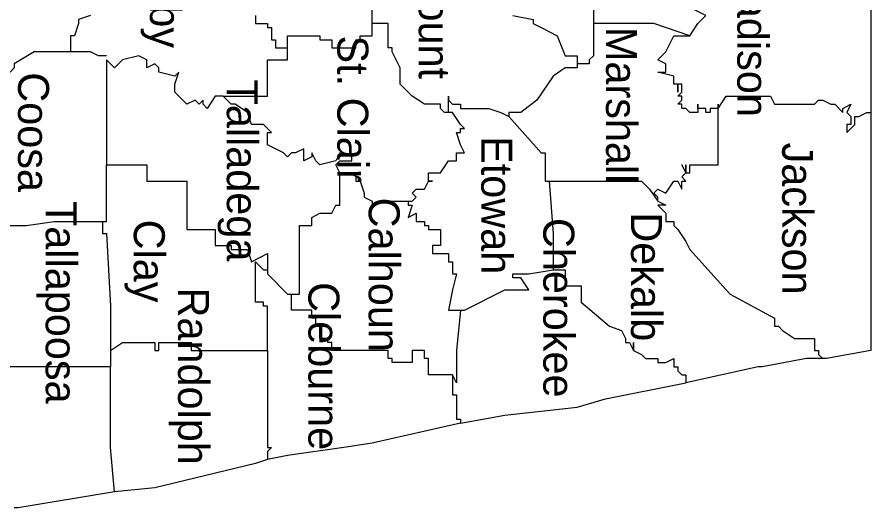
# Model space of a CAD drawing. Extents: x 0 to 0.917, y 0 to 0.708.
# Drawn here: x 0.4862 to 0.6298, y 0.4444 to 0.5269 of the extents above; entities that cross this region are included whole.
import ezdxf

# ---------------------------------------------------------------- set-up
doc = ezdxf.new("R2010")
doc.units = 0
doc.layers.add('ANNO-SHT', color=7, linetype='Continuous')
doc.layers.add('ANNO-TXT', color=7, linetype='Continuous')

msp = doc.modelspace()

# ---------------------------------------------------------------- linework, layer by layer
at = {"layer": 'ANNO-SHT'}
for points in [[(0.62981, 0.5618), (0.62981, 0.55161), (0.62981, 0.54347), (0.62981, 0.54143), (0.62981, 0.53736), (0.62981, 0.52718), (0.62981, 0.51089), (0.62981, 0.5075), (0.62981, 0.49732), (0.62981, 0.48781), (0.62981, 0.47763), (0.62981, 0.47085), (0.62981, 0.47085), (0.62236, 0.46949), (0.62169, 0.46949), (0.61898, 0.46949), (0.61154, 0.46813), (0.61086, 0.46813), (0.59868, 0.46542), (0.59868, 0.46542)], [(0.58312, 0.55637), (0.58312, 0.55501), (0.58312, 0.54958), (0.58312, 0.54415), (0.58312, 0.54347), (0.58312, 0.52718), (0.58312, 0.52582)], [(0.59936, 0.52379), (0.60071, 0.52582), (0.60206, 0.52718), (0.59936, 0.52854), (0.60003, 0.53057), (0.60206, 0.53261), (0.60206, 0.53397), (0.59936, 0.53533), (0.59936, 0.53736), (0.59936, 0.53804), (0.60003, 0.54143), (0.60206, 0.54415), (0.60409, 0.5489), (0.60545, 0.54958), (0.6068, 0.55161), (0.60612, 0.55229), (0.60748, 0.55501), (0.60815, 0.55637)], [(0.55876, 0.51089), (0.55808, 0.51089), (0.55808, 0.51089), (0.55808, 0.51089), (0.5574, 0.51157), (0.5574, 0.51225), (0.55605, 0.51225), (0.55537, 0.51225), (0.55537, 0.51225), (0.55537, 0.51225), (0.5547, 0.51225), (0.55267, 0.51361), (0.55064, 0.51564), (0.55064, 0.51768), (0.55064, 0.51836), (0.54928, 0.52107), (0.54928, 0.52175), (0.54861, 0.52175), (0.54861, 0.52175), (0.54861, 0.52582), (0.5459, 0.52582), (0.5459, 0.52854)], [(0.49853, 0.52718), (0.4965, 0.5265), (0.4965, 0.5265), (0.4965, 0.52582), (0.49583, 0.52379), (0.49515, 0.52379), (0.49515, 0.52311), (0.49515, 0.52175), (0.49515, 0.52175), (0.49515, 0.52107)], [(0.49853, 0.52718), (0.4965, 0.5265), (0.4965, 0.5265), (0.4965, 0.52582), (0.49583, 0.52379), (0.49515, 0.52379), (0.49515, 0.52311), (0.49515, 0.52175), (0.49515, 0.52175), (0.49515, 0.52107)], [(0.52628, 0.52718), (0.52628, 0.5265), (0.52628, 0.5265), (0.52628, 0.52582), (0.52763, 0.52582), (0.52763, 0.52582), (0.52831, 0.52582), (0.52831, 0.52582), (0.52831, 0.52582), (0.52831, 0.52514), (0.52898, 0.52514), (0.52898, 0.52379), (0.52898, 0.52379), (0.52898, 0.52379), (0.52898, 0.52311), (0.52966, 0.52311), (0.52966, 0.52175), (0.53169, 0.52175)], [(0.56958, 0.52718), (0.57297, 0.5265), (0.57297, 0.52582), (0.57432, 0.52514), (0.57703, 0.52379), (0.57838, 0.52039), (0.58041, 0.52039), (0.58041, 0.51904), (0.58041, 0.51836), (0.57838, 0.51836), (0.57635, 0.517), (0.57364, 0.51293), (0.57094, 0.51089), (0.56958, 0.51089), (0.56958, 0.51089), (0.56891, 0.51089), (0.56891, 0.51021)], [(0.52086, 0.51361), (0.52492, 0.51361), (0.52831, 0.51361), (0.52831, 0.51971), (0.53169, 0.51971), (0.53169, 0.52175), (0.53169, 0.52175), (0.53169, 0.52175), (0.53169, 0.52311), (0.53169, 0.52379), (0.53237, 0.52379), (0.53237, 0.52379), (0.53575, 0.52379), (0.53643, 0.52379), (0.5371, 0.52379), (0.5371, 0.52311), (0.53913, 0.52311), (0.53913, 0.52175), (0.54116, 0.52175), (0.54116, 0.52175), (0.54319, 0.52175), (0.54319, 0.52311), (0.54387, 0.52311), (0.54387, 0.52379), (0.5459, 0.52379), (0.5459, 0.52582)], [(0.59936, 0.52379), (0.59327, 0.52582), (0.58785, 0.52582), (0.58312, 0.52582), (0.58312, 0.52379), (0.58312, 0.52107), (0.58312, 0.52039), (0.58244, 0.51971), (0.58244, 0.51904), (0.58109, 0.51904), (0.58109, 0.51904), (0.58041, 0.51904), (0.58041, 0.51904), (0.58041, 0.51904)], [(0.57567, 0.49935), (0.58041, 0.49935), (0.58176, 0.49935), (0.58312, 0.49935), (0.58988, 0.49935), (0.58988, 0.49935), (0.58988, 0.49935), (0.58988, 0.49935), (0.59124, 0.49935), (0.59259, 0.498), (0.59394, 0.49596), (0.59394, 0.49664), (0.59327, 0.49732), (0.59394, 0.498), (0.5953, 0.49732), (0.59665, 0.49935), (0.59733, 0.49935), (0.59733, 0.49935), (0.598, 0.498), (0.598, 0.49935), (0.59868, 0.49935), (0.598, 0.50003), (0.59868, 0.50071), (0.598, 0.50207), (0.59868, 0.50071), (0.59868, 0.50207), (0.59868, 0.50207), (0.59868, 0.50207), (0.59868, 0.50207), (0.59868, 0.50207), (0.59868, 0.50207), (0.59868, 0.50071), (0.59936, 0.50071), (0.59936, 0.50207), (0.60003, 0.50207), (0.60003, 0.50207), (0.60409, 0.50207), (0.60409, 0.51157), (0.60274, 0.51157), (0.60274, 0.51089), (0.60274, 0.51089), (0.60274, 0.51089), (0.60206, 0.51089), (0.60206, 0.51089), (0.60206, 0.51157), (0.60071, 0.51157), (0.60071, 0.51225), (0.60071, 0.51225), (0.60071, 0.51089), (0.59936, 0.51089), (0.59936, 0.51089), (0.59868, 0.51157), (0.598, 0.51157), (0.598, 0.51225), (0.59733, 0.51225), (0.59733, 0.51225), (0.59733, 0.51225), (0.598, 0.51293), (0.598, 0.51361), (0.59733, 0.51361), (0.598, 0.51428), (0.598, 0.51564), (0.598, 0.51564), (0.59733, 0.51564), (0.59733, 0.51564), (0.59733, 0.51428), (0.59733, 0.51564), (0.59665, 0.51564), (0.59665, 0.51564), (0.59665, 0.51564), (0.59665, 0.51564), (0.59665, 0.517), (0.59394, 0.51768), (0.5953, 0.51768), (0.5953, 0.51904), (0.59394, 0.51971), (0.59394, 0.51971), (0.5953, 0.52107), (0.59665, 0.52379), (0.59733, 0.52379), (0.59868, 0.52379), (0.59936, 0.52379)], [(0.49515, 0.52107), (0.49312, 0.52107), (0.49244, 0.52107), (0.49109, 0.52107), (0.48974, 0.52107), (0.48906, 0.52107), (0.48568, 0.51904), (0.48568, 0.51836), (0.485, 0.51768), (0.48432, 0.51768), (0.48432, 0.51768), (0.48162, 0.51768), (0.47959, 0.517), (0.47959, 0.51564), (0.47891, 0.51564), (0.47756, 0.51293)], [(0.49515, 0.52107), (0.49312, 0.52107), (0.49244, 0.52107), (0.49109, 0.52107), (0.48974, 0.52107), (0.48906, 0.52107), (0.48568, 0.51904), (0.48568, 0.51836), (0.485, 0.51768), (0.48432, 0.51768), (0.48432, 0.51768), (0.48162, 0.51768), (0.47959, 0.517), (0.47959, 0.51564), (0.47891, 0.51564), (0.47756, 0.51293)], [(0.50124, 0.52039), (0.50056, 0.52039), (0.49989, 0.52039), (0.49853, 0.52107), (0.4965, 0.52107), (0.49515, 0.52107)], [(0.50124, 0.52039), (0.50056, 0.52039), (0.49989, 0.52039), (0.49853, 0.52107), (0.4965, 0.52107), (0.49515, 0.52107)], [(0.54049, 0.50071), (0.54049, 0.50071), (0.53981, 0.50207), (0.54049, 0.50275), (0.54252, 0.50275), (0.54252, 0.50343), (0.54049, 0.5041), (0.53981, 0.50275), (0.5371, 0.50207), (0.53643, 0.50275), (0.53575, 0.5041), (0.53575, 0.50343), (0.5344, 0.50275), (0.5344, 0.50275), (0.5344, 0.50275), (0.5344, 0.50478), (0.53304, 0.5041), (0.53237, 0.5041), (0.53169, 0.50343), (0.53101, 0.5041), (0.52966, 0.50478), (0.52831, 0.50546), (0.52831, 0.5075), (0.52898, 0.5075), (0.52763, 0.50886), (0.5256, 0.50886), (0.52492, 0.51089), (0.52289, 0.51225), (0.52222, 0.51225), (0.52086, 0.51361), (0.51951, 0.51361), (0.51816, 0.51157), (0.51748, 0.51225), (0.51748, 0.51293), (0.5168, 0.51225), (0.51613, 0.51293), (0.51477, 0.51225), (0.51477, 0.51225), (0.51274, 0.51428), (0.51274, 0.51564), (0.51342, 0.51768), (0.51274, 0.517), (0.51004, 0.51768), (0.51004, 0.51836), (0.50936, 0.51904), (0.50801, 0.51836), (0.50801, 0.51904), (0.50801, 0.51971), (0.50665, 0.52039), (0.50665, 0.52039), (0.50395, 0.51971), (0.50327, 0.51904), (0.50259, 0.51836), (0.50192, 0.51904), (0.50124, 0.51971)], [(0.54049, 0.50071), (0.54049, 0.50071), (0.53981, 0.50207), (0.54049, 0.50275), (0.54252, 0.50275), (0.54252, 0.50343), (0.54049, 0.5041), (0.53981, 0.50275), (0.5371, 0.50207), (0.53643, 0.50275), (0.53575, 0.5041), (0.53575, 0.50343), (0.5344, 0.50275), (0.5344, 0.50275), (0.5344, 0.50275), (0.5344, 0.50478), (0.53304, 0.5041), (0.53237, 0.5041), (0.53169, 0.50343), (0.53101, 0.5041), (0.52966, 0.50478), (0.52831, 0.50546), (0.52831, 0.5075), (0.52898, 0.5075), (0.52763, 0.50886), (0.5256, 0.50886), (0.52492, 0.51089), (0.52289, 0.51225), (0.52222, 0.51225), (0.52086, 0.51361), (0.51951, 0.51361), (0.51816, 0.51157), (0.51748, 0.51225), (0.51748, 0.51293), (0.5168, 0.51225), (0.51613, 0.51293), (0.51477, 0.51225), (0.51477, 0.51225), (0.51274, 0.51428), (0.51274, 0.51564), (0.51342, 0.51768), (0.51274, 0.517), (0.51004, 0.51768), (0.51004, 0.51836), (0.50936, 0.51904), (0.50801, 0.51836), (0.50801, 0.51904), (0.50801, 0.51971), (0.50665, 0.52039), (0.50665, 0.52039), (0.50395, 0.51971), (0.50327, 0.51904), (0.50259, 0.51836), (0.50192, 0.51904), (0.50124, 0.51971)], [(0.50124, 0.51971), (0.50124, 0.50546), (0.50124, 0.50478), (0.50124, 0.50207)], [(0.55199, 0.49596), (0.55199, 0.49596), (0.55199, 0.49596), (0.55199, 0.49596), (0.55267, 0.49596), (0.55267, 0.49596), (0.55334, 0.49664), (0.55267, 0.49732), (0.55267, 0.49732), (0.55267, 0.49732), (0.55334, 0.498), (0.5547, 0.498), (0.55537, 0.49935), (0.55605, 0.49935), (0.55537, 0.49935), (0.55537, 0.50003), (0.55537, 0.50071), (0.55605, 0.50071), (0.5574, 0.50071), (0.55876, 0.50275), (0.55943, 0.50275), (0.56011, 0.50275), (0.56011, 0.5041), (0.56079, 0.5041), (0.56146, 0.5041), (0.56079, 0.50546), (0.56079, 0.50546), (0.56011, 0.5075), (0.56079, 0.5075), (0.56079, 0.50818), (0.56146, 0.50818), (0.56079, 0.50886), (0.56079, 0.50886), (0.55943, 0.51089), (0.55876, 0.51089), (0.55876, 0.51361), (0.55876, 0.51361), (0.55876, 0.51293), (0.55943, 0.51225), (0.55943, 0.51225), (0.55943, 0.51225), (0.55943, 0.51225), (0.56011, 0.51225), (0.56011, 0.51225), (0.56011, 0.51225), (0.56079, 0.51225), (0.56079, 0.51157), (0.56079, 0.51157), (0.56146, 0.51157), (0.56417, 0.51157), (0.56552, 0.51157), (0.56755, 0.51089), (0.56755, 0.51089), (0.56891, 0.51021)], [(0.60409, 0.51157), (0.60409, 0.51225), (0.60409, 0.51157), (0.60545, 0.51361), (0.60883, 0.51361), (0.61289, 0.51361), (0.61357, 0.51225), (0.61424, 0.51225), (0.61492, 0.51225), (0.6156, 0.51225), (0.6156, 0.51225), (0.61695, 0.51225), (0.61695, 0.51225), (0.61763, 0.51225), (0.6183, 0.51225), (0.61898, 0.51225), (0.61898, 0.51225), (0.62033, 0.51225), (0.62101, 0.51293), (0.62169, 0.51293), (0.62169, 0.51293), (0.62304, 0.51225), (0.62304, 0.51225), (0.62372, 0.51225), (0.62507, 0.51089), (0.62507, 0.51157), (0.62642, 0.51225), (0.62575, 0.51089), (0.62642, 0.51021), (0.62642, 0.51021), (0.62642, 0.50886), (0.62575, 0.50886), (0.62575, 0.50886), (0.62575, 0.50886), (0.62575, 0.50818), (0.62575, 0.5075), (0.62642, 0.50818), (0.6271, 0.50886), (0.6271, 0.51021), (0.62778, 0.51021), (0.62913, 0.51089), (0.62981, 0.51089)], [(0.56891, 0.51021), (0.57432, 0.5041), (0.575, 0.5041), (0.575, 0.50343), (0.575, 0.50275), (0.575, 0.50275), (0.575, 0.50207), (0.575, 0.50071), (0.575, 0.49935), (0.57567, 0.49935), (0.57635, 0.49053), (0.57635, 0.48917), (0.57635, 0.48781), (0.57635, 0.48442), (0.57838, 0.48442), (0.57838, 0.48306), (0.57838, 0.48306), (0.57838, 0.48171), (0.57838, 0.48171), (0.58109, 0.48171), (0.58109, 0.47899), (0.58582, 0.47492), (0.58785, 0.47424), (0.58853, 0.47288), (0.58853, 0.47288), (0.58853, 0.4722), (0.58853, 0.4722), (0.58921, 0.4722), (0.58988, 0.47085), (0.58988, 0.4722), (0.58988, 0.47085), (0.58988, 0.47085), (0.59124, 0.47017), (0.59124, 0.47017), (0.59191, 0.46949), (0.59191, 0.46949), (0.59191, 0.46949), (0.59394, 0.46949), (0.59394, 0.46949), (0.59394, 0.46949), (0.59394, 0.46881), (0.5953, 0.46881), (0.59665, 0.46949), (0.59665, 0.46813), (0.59733, 0.46813), (0.59733, 0.46745), (0.598, 0.46677), (0.598, 0.46677), (0.59868, 0.46677), (0.59868, 0.46677), (0.59868, 0.46542)], [(0.56891, 0.51021), (0.57432, 0.5041), (0.575, 0.5041), (0.575, 0.50343), (0.575, 0.50275), (0.575, 0.50275), (0.575, 0.50207), (0.575, 0.50071), (0.575, 0.49935), (0.57567, 0.49935), (0.57635, 0.49053), (0.57635, 0.48917), (0.57635, 0.48781), (0.57635, 0.48442), (0.57838, 0.48442), (0.57838, 0.48306), (0.57838, 0.48306), (0.57838, 0.48171), (0.57838, 0.48171), (0.58109, 0.48171), (0.58109, 0.47899), (0.58582, 0.47492), (0.58785, 0.47424), (0.58853, 0.47288), (0.58853, 0.47288), (0.58853, 0.4722), (0.58853, 0.4722), (0.58921, 0.4722), (0.58988, 0.47085), (0.58988, 0.4722), (0.58988, 0.47085), (0.58988, 0.47085), (0.59124, 0.47017), (0.59124, 0.47017), (0.59191, 0.46949), (0.59191, 0.46949), (0.59191, 0.46949), (0.59394, 0.46949), (0.59394, 0.46949), (0.59394, 0.46949), (0.59394, 0.46881), (0.5953, 0.46881), (0.59665, 0.46949), (0.59665, 0.46813), (0.59733, 0.46813), (0.59733, 0.46745), (0.598, 0.46677), (0.598, 0.46677), (0.59868, 0.46677), (0.59868, 0.46677), (0.59868, 0.46542)], [(0.47756, 0.49189), (0.48162, 0.49189), (0.48297, 0.49257), (0.48297, 0.49189), (0.48297, 0.49189), (0.48297, 0.49257), (0.48297, 0.49257), (0.48297, 0.49189), (0.48703, 0.49189), (0.48771, 0.49189), (0.49244, 0.49257), (0.50056, 0.49257), (0.50124, 0.49257), (0.50124, 0.49257), (0.50124, 0.50207)], [(0.50124, 0.50207), (0.50665, 0.50207), (0.50801, 0.50207), (0.50801, 0.49935), (0.51477, 0.49935), (0.51477, 0.49257), (0.51477, 0.49189), (0.51477, 0.49121), (0.51951, 0.49121), (0.51951, 0.48849), (0.52222, 0.48849), (0.52222, 0.48781), (0.52492, 0.48781), (0.5256, 0.48578), (0.52831, 0.48714), (0.52831, 0.48374), (0.53169, 0.48035), (0.53237, 0.48035), (0.53372, 0.48035), (0.53372, 0.48374), (0.53372, 0.4851), (0.53372, 0.49189), (0.53575, 0.49189), (0.53575, 0.49324), (0.53575, 0.49324), (0.53575, 0.49324), (0.5371, 0.49392), (0.53846, 0.49392), (0.53846, 0.49392), (0.53913, 0.49392), (0.53913, 0.49392), (0.53981, 0.49528), (0.54049, 0.49528), (0.54049, 0.49664), (0.54049, 0.50071)], [(0.54049, 0.50071), (0.54252, 0.50071), (0.54319, 0.50003), (0.54319, 0.49935), (0.54387, 0.49935), (0.54455, 0.49732), (0.54455, 0.49664), (0.5459, 0.49596), (0.5459, 0.49528), (0.54793, 0.49596), (0.54793, 0.49596), (0.54861, 0.49596), (0.54928, 0.49596), (0.55064, 0.49596), (0.55131, 0.49596), (0.55199, 0.49596)], [(0.55199, 0.49596), (0.55199, 0.49596), (0.55199, 0.49528), (0.55267, 0.49528), (0.55199, 0.49324), (0.55334, 0.49392), (0.55334, 0.49257), (0.5547, 0.49257), (0.5547, 0.49189), (0.55537, 0.49189), (0.55537, 0.49121), (0.5574, 0.49121), (0.5574, 0.48917), (0.5574, 0.48917), (0.5574, 0.48849), (0.55605, 0.48849), (0.55605, 0.48781), (0.55605, 0.48714), (0.55876, 0.48714), (0.55876, 0.48578), (0.55943, 0.48578), (0.55943, 0.48374), (0.56011, 0.48374), (0.55943, 0.48103), (0.55876, 0.47763), (0.56011, 0.47763), (0.56079, 0.47763), (0.56011, 0.47085), (0.56011, 0.46813), (0.56011, 0.46542), (0.55943, 0.46677), (0.55943, 0.46338), (0.56011, 0.46338), (0.56011, 0.45999), (0.56011, 0.45999), (0.56011, 0.45999), (0.56011, 0.45999), (0.56011, 0.45931), (0.56079, 0.45931), (0.56079, 0.45931), (0.56079, 0.45863)], [(0.59394, 0.49596), (0.59394, 0.49596), (0.5953, 0.49528), (0.59394, 0.49528), (0.5953, 0.49392), (0.5953, 0.49324), (0.5953, 0.49257), (0.59665, 0.49257), (0.59665, 0.49189), (0.59733, 0.49121), (0.59868, 0.48917), (0.59936, 0.48781), (0.60545, 0.48103), (0.60612, 0.48035), (0.61357, 0.47628), (0.61357, 0.47492), (0.61424, 0.47492), (0.61492, 0.47424), (0.61695, 0.47288), (0.61763, 0.47288), (0.6183, 0.47288), (0.62033, 0.47288), (0.62033, 0.4722), (0.62033, 0.47085), (0.62101, 0.47085), (0.62101, 0.47085), (0.62101, 0.47017), (0.62169, 0.46949)], [(0.50056, 0.49257), (0.50056, 0.49053), (0.50124, 0.49053), (0.50124, 0.49053), (0.50192, 0.47831), (0.50192, 0.47085), (0.50395, 0.4722), (0.50936, 0.4722), (0.50936, 0.47085), (0.51004, 0.47085), (0.51004, 0.4722), (0.51545, 0.4722), (0.51545, 0.47085), (0.51613, 0.47085), (0.51613, 0.47085), (0.5168, 0.47085), (0.5168, 0.47085), (0.5168, 0.47085), (0.5168, 0.47085), (0.52831, 0.47085), (0.52831, 0.47288), (0.52831, 0.47831), (0.52763, 0.47831), (0.52763, 0.47899), (0.52763, 0.47899), (0.52628, 0.47899), (0.52628, 0.48306), (0.52628, 0.48578), (0.52628, 0.48578), (0.52763, 0.48442), (0.52831, 0.48442), (0.52831, 0.48374), (0.52831, 0.48374)], [(0.56079, 0.47763), (0.56146, 0.47763), (0.56823, 0.48103), (0.56891, 0.48103), (0.57094, 0.48103), (0.57094, 0.48103), (0.57229, 0.48103), (0.57229, 0.48103), (0.57229, 0.48103), (0.57094, 0.48306), (0.56958, 0.48306), (0.56958, 0.48374), (0.57094, 0.48374), (0.57229, 0.48374), (0.57635, 0.48442)], [(0.55943, 0.46677), (0.55876, 0.46677), (0.55537, 0.46677), (0.55537, 0.46949), (0.5547, 0.46949), (0.5547, 0.47085), (0.55267, 0.47085), (0.55267, 0.46881), (0.54928, 0.46881), (0.54928, 0.46949), (0.54861, 0.46949), (0.54861, 0.47085), (0.54725, 0.47085), (0.54725, 0.47085), (0.53913, 0.47085), (0.53913, 0.4722), (0.53913, 0.4722), (0.53846, 0.4722), (0.53846, 0.4722), (0.53846, 0.4722), (0.53846, 0.47288), (0.5371, 0.47288), (0.5371, 0.47492), (0.53643, 0.47492), (0.53643, 0.47492), (0.53643, 0.47628), (0.53643, 0.47628), (0.53575, 0.47628), (0.53575, 0.47763), (0.53237, 0.47763), (0.53237, 0.48035)], [(0.50192, 0.47085), (0.50192, 0.46813), (0.50124, 0.46813), (0.48297, 0.46813), (0.4762, 0.46813)], [(0.52831, 0.47085), (0.52831, 0.46881), (0.52831, 0.45456), (0.52898, 0.45456), (0.52898, 0.45456), (0.52831, 0.45388), (0.52831, 0.4532), (0.52831, 0.45252), (0.52831, 0.45252)], [(0.50259, 0.44709), (0.50192, 0.45456), (0.50192, 0.46406), (0.50192, 0.46813), (0.50192, 0.46813)], [(0.56079, 0.45863), (0.56823, 0.45999), (0.58041, 0.46134), (0.58515, 0.4627), (0.59868, 0.46542)], [(0.56079, 0.45863), (0.5459, 0.45524), (0.54116, 0.45456), (0.53169, 0.4532), (0.52831, 0.45252), (0.52628, 0.45184), (0.50936, 0.44777), (0.50259, 0.44709), (0.48635, 0.44438), (0.48635, 0.44438), (0.48568, 0.44438)]]:
    msp.add_lwpolyline(points, dxfattribs=at)

# ---------------------------------------------------------------- texts
at = {"layer": 'ANNO-TXT'}
for s, p in [('Shelby', (0.50854, 0.54301)), ('Madison', (0.60733, 0.53646)), ('Blount', (0.55376, 0.53624)), ('Marshall', (0.58525, 0.52527)), ('St. Clair', (0.54005, 0.52382)), ('Coosa', (0.48636, 0.51763)), ('Talladega', (0.52147, 0.51642)), ('Etowah', (0.56427, 0.5069)), ('Jackson', (0.61488, 0.50581)), ('Tallapoosa', (0.49101, 0.49599)), ('Calhoun', (0.54533, 0.49656)), ('Cherokee', (0.5747, 0.49314)), ('Dekalb', (0.58945, 0.49408)), ('Clay', (0.50582, 0.49286)), ('Cleburne', (0.53519, 0.48235)), ('Randolph', (0.51327, 0.48144))]:
    msp.add_text(s, height=0.005208, rotation=270, dxfattribs=at).set_placement(p)

doc.saveas('drawing.dxf')
